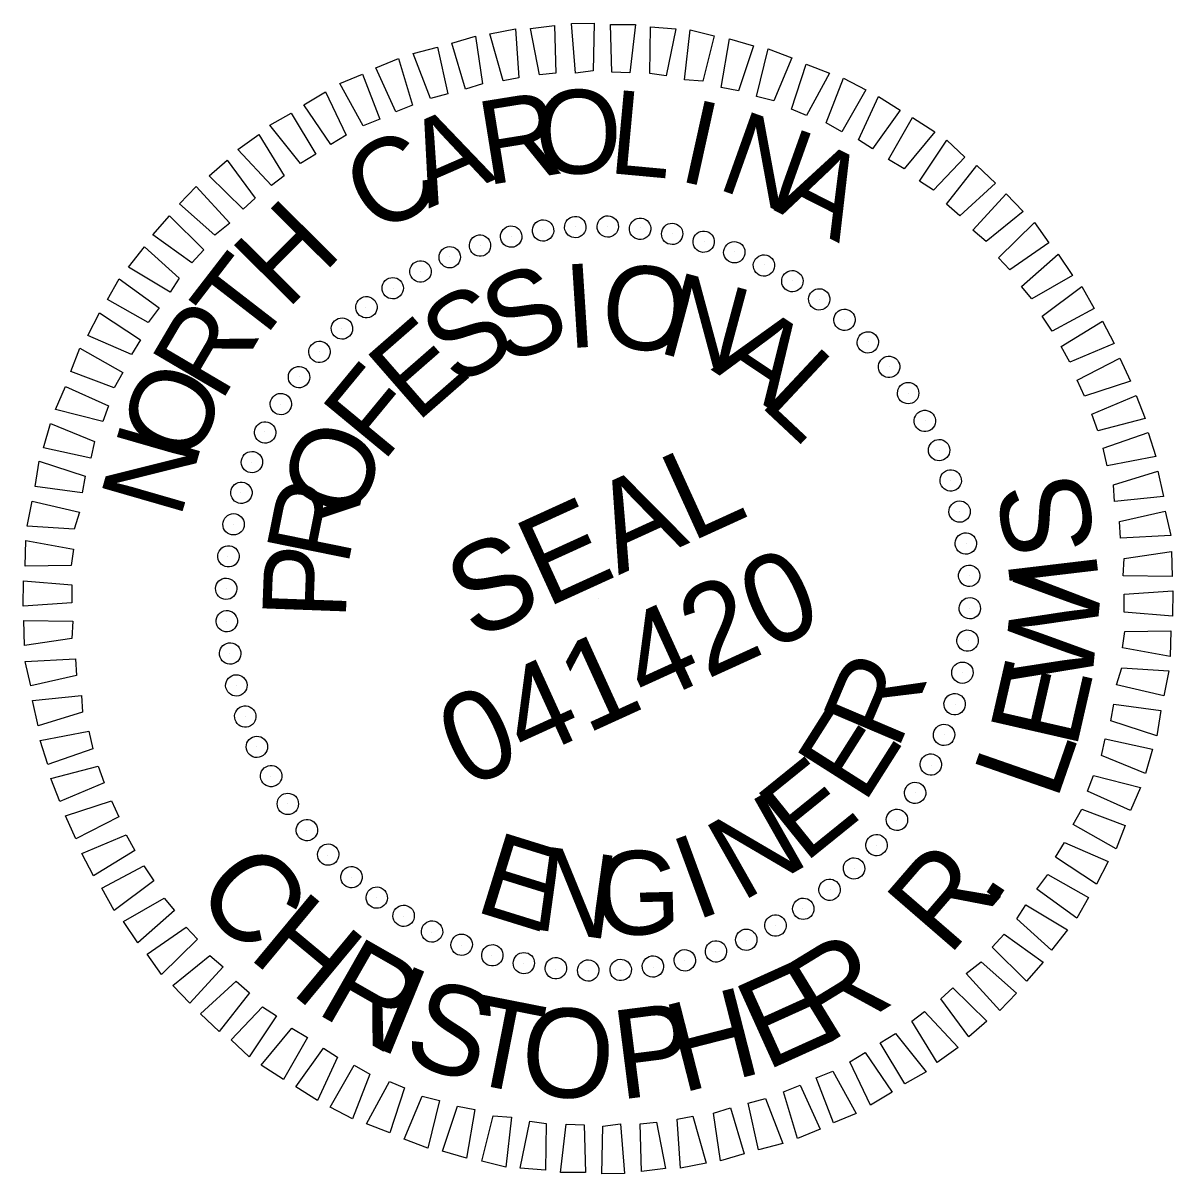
# Model space of a CAD drawing. Extents: x 2246788 to 2250969, y 662010 to 664598.
# Drawn here: x 2248634.4 to 2248712, y 663700.9 to 663778.5 of the extents above; entities that cross this region are included whole.
import ezdxf

# ---------------------------------------------------------------- set-up
doc = ezdxf.new("R2010")
doc.units = 0
doc.layers.add('Sheet PE Seal Cell', color=7, linetype='Continuous')

msp = doc.modelspace()

# ---------------------------------------------------------------- linework, layer by layer
at = {"layer": 'Sheet PE Seal Cell'}
for p, q in [((2248671.685, 663764.801), (2248671.685, 663764.801)), ((2248673.878, 663764.811), (2248673.878, 663764.811)), ((2248676.067, 663764.71), (2248676.067, 663764.71)), ((2248667.386, 663764.106), (2248667.386, 663764.106)), ((2248669.483, 663764.567), (2248669.483, 663764.567)), ((2248678.223, 663764.319), (2248678.223, 663764.319)), ((2248665.284, 663763.533), (2248665.284, 663763.533)), ((2248680.375, 663763.816), (2248680.375, 663763.816)), ((2248682.408, 663763.093), (2248682.408, 663763.093)), ((2248663.22, 663762.757), (2248663.22, 663762.757)), ((2248661.239, 663761.799), (2248661.239, 663761.799)), ((2248684.457, 663762.214), (2248684.457, 663762.214)), ((2248686.32, 663761.14), (2248686.32, 663761.14)), ((2248659.407, 663760.635), (2248659.407, 663760.635)), ((2248657.571, 663759.358), (2248657.571, 663759.358)), ((2248688.154, 663759.888), (2248688.154, 663759.888)), ((2248689.873, 663758.528), (2248689.873, 663758.528)), ((2248655.909, 663757.941), (2248655.909, 663757.941)), ((2248691.43, 663757.04), (2248691.43, 663757.04)), ((2248654.42, 663756.384), (2248654.42, 663756.384)), ((2248692.847, 663755.378), (2248692.847, 663755.378)), ((2248653.061, 663754.666), (2248653.061, 663754.666)), ((2248694.123, 663753.542), (2248694.123, 663753.542)), ((2248651.808, 663752.831), (2248651.808, 663752.831)), ((2248695.288, 663751.709), (2248695.288, 663751.709)), ((2248650.734, 663750.968), (2248650.734, 663750.968)), ((2248696.246, 663749.728), (2248696.246, 663749.728)), ((2248649.855, 663748.919), (2248649.855, 663748.919)), ((2248697.021, 663747.664), (2248697.021, 663747.664)), ((2248649.133, 663746.887), (2248649.133, 663746.887)), ((2248697.594, 663745.563), (2248697.594, 663745.563)), ((2248648.63, 663744.734), (2248648.63, 663744.734)), ((2248698.056, 663743.465), (2248698.056, 663743.465)), ((2248648.239, 663742.578), (2248648.239, 663742.578)), ((2248698.289, 663741.264), (2248698.289, 663741.264)), ((2248648.137, 663740.389), (2248648.137, 663740.389)), ((2248673.219, 663739.73), (2248673.219, 663739.73)), ((2248698.3, 663739.071), (2248698.3, 663739.071)), ((2248648.148, 663738.196), (2248648.148, 663738.196)), ((2248698.198, 663736.882), (2248698.198, 663736.882)), ((2248648.381, 663735.995), (2248648.381, 663735.995)), ((2248697.807, 663734.725), (2248697.807, 663734.725)), ((2248648.843, 663733.897), (2248648.843, 663733.897)), ((2248697.305, 663732.573), (2248697.305, 663732.573)), ((2248649.416, 663731.795), (2248649.416, 663731.795)), ((2248696.582, 663730.541), (2248696.582, 663730.541)), ((2248650.192, 663729.731), (2248650.192, 663729.731)), ((2248695.703, 663728.491), (2248695.703, 663728.491)), ((2248651.149, 663727.75), (2248651.149, 663727.75)), ((2248694.629, 663726.628), (2248694.629, 663726.628)), ((2248652.314, 663725.918), (2248652.314, 663725.918)), ((2248693.377, 663724.794), (2248693.377, 663724.794)), ((2248653.59, 663724.082), (2248653.59, 663724.082)), ((2248692.017, 663723.075), (2248692.017, 663723.075)), ((2248655.007, 663722.42), (2248655.007, 663722.42)), ((2248690.529, 663721.518), (2248690.529, 663721.518)), ((2248656.564, 663720.932), (2248656.564, 663720.932)), ((2248688.866, 663720.101), (2248688.866, 663720.101)), ((2248658.283, 663719.572), (2248658.283, 663719.572)), ((2248660.117, 663718.32), (2248660.117, 663718.32)), ((2248687.03, 663718.825), (2248687.03, 663718.825)), ((2248685.198, 663717.661), (2248685.198, 663717.661)), ((2248661.98, 663717.246), (2248661.98, 663717.246)), ((2248683.217, 663716.703), (2248683.217, 663716.703)), ((2248664.029, 663716.366), (2248664.029, 663716.366)), ((2248681.153, 663715.927), (2248681.153, 663715.927)), ((2248666.062, 663715.644), (2248666.062, 663715.644)), ((2248668.214, 663715.141), (2248668.214, 663715.141)), ((2248679.051, 663715.354), (2248679.051, 663715.354)), ((2248670.37, 663714.75), (2248670.37, 663714.75)), ((2248672.559, 663714.649), (2248672.559, 663714.649)), ((2248674.753, 663714.659), (2248674.753, 663714.659)), ((2248676.954, 663714.893), (2248676.954, 663714.893))]:
    msp.add_line(p, q, dxfattribs=at)
for points in [[(2248666.826, 663774.62), (2248665.933, 663777.785), (2248667.646, 663778.125), (2248667.885, 663774.828)], [(2248669.279, 663775.023), (2248668.676, 663778.155), (2248670.294, 663778.343), (2248670.38, 663775.14)], [(2248671.7, 663775.137), (2248671.44, 663778.481), (2248672.963, 663778.515), (2248672.891, 663775.296)], [(2248674.141, 663775.206), (2248674.055, 663778.409), (2248675.756, 663778.414), (2248675.37, 663775.162)], [(2248676.711, 663775.113), (2248676.758, 663778.266), (2248678.475, 663778.115), (2248677.824, 663774.961)], [(2248679.045, 663774.693), (2248679.435, 663778.058), (2248681.053, 663777.642), (2248680.295, 663774.604)], [(2248664.277, 663774.063), (2248663.36, 663777.161), (2248664.965, 663777.618), (2248665.431, 663774.424)], [(2248681.533, 663774.178), (2248682.076, 663777.448), (2248683.715, 663776.986), (2248682.687, 663773.935)], [(2248661.927, 663773.432), (2248660.762, 663776.472), (2248662.387, 663776.883), (2248663.102, 663773.747)], [(2248683.904, 663773.556), (2248684.692, 663776.772), (2248686.281, 663776.177), (2248685.08, 663773.267)], [(2248659.59, 663772.532), (2248658.242, 663775.489), (2248659.765, 663776.128), (2248660.703, 663772.984)], [(2248686.268, 663772.71), (2248687.25, 663775.74), (2248688.839, 663775.145), (2248687.282, 663772.293)], [(2248657.385, 663771.582), (2248655.81, 663774.436), (2248657.332, 663775.074), (2248658.498, 663772.034)], [(2248688.607, 663771.797), (2248689.767, 663774.799), (2248691.282, 663774.006), (2248689.658, 663771.178)], [(2248655.214, 663770.318), (2248653.387, 663773.002), (2248654.851, 663773.888), (2248656.244, 663770.952)], [(2248690.78, 663770.645), (2248692.139, 663773.572), (2248693.605, 663772.646), (2248691.72, 663770.029)], [(2248653.155, 663769.05), (2248651.1, 663771.63), (2248652.539, 663772.45), (2248654.184, 663769.684)], [(2248692.813, 663769.319), (2248694.437, 663772.146), (2248695.923, 663771.175), (2248693.865, 663768.699)], [(2248651.199, 663767.554), (2248648.937, 663769.985), (2248650.339, 663771.008), (2248652.051, 663768.217)], [(2248694.908, 663767.856), (2248696.731, 663770.609), (2248697.965, 663769.468), (2248695.848, 663767.24)], [(2248649.284, 663765.967), (2248646.994, 663768.22), (2248648.218, 663769.272), (2248650.095, 663766.721)], [(2248696.71, 663766.314), (2248698.772, 663768.902), (2248700.027, 663767.716), (2248697.621, 663765.52)], [(2248647.387, 663764.223), (2248645.001, 663766.323), (2248646.117, 663767.491), (2248648.4, 663765.015)], [(2248698.503, 663764.549), (2248700.74, 663766.996), (2248701.883, 663765.814), (2248699.394, 663763.801)], [(2248645.82, 663762.356), (2248643.203, 663764.24), (2248644.323, 663765.52), (2248646.634, 663763.221)], [(2248700.227, 663762.696), (2248702.662, 663765.07), (2248703.619, 663763.693), (2248700.98, 663761.886)], [(2248644.361, 663760.372), (2248641.558, 663762.062), (2248642.637, 663763.433), (2248644.977, 663761.312)], [(2248701.768, 663760.761), (2248704.24, 663762.932), (2248705.218, 663761.509), (2248702.476, 663759.93)], [(2248642.878, 663758.322), (2248640.137, 663759.876), (2248640.926, 663761.279), (2248643.63, 663759.324)], [(2248703.172, 663758.764), (2248705.84, 663760.749), (2248706.681, 663759.264), (2248703.852, 663757.755)], [(2248641.771, 663756.17), (2248638.819, 663757.462), (2248639.612, 663758.977), (2248642.366, 663757.155)], [(2248704.441, 663756.704), (2248707.232, 663758.416), (2248708.028, 663756.911), (2248705.029, 663755.654)], [(2248640.593, 663753.93), (2248637.679, 663755.019), (2248638.274, 663756.609), (2248641.168, 663754.961)], [(2248705.523, 663754.45), (2248708.418, 663755.934), (2248709.123, 663754.387), (2248706.02, 663753.358)], [(2248639.818, 663751.653), (2248636.647, 663752.461), (2248637.308, 663754.026), (2248640.214, 663752.713)], [(2248706.514, 663752.155), (2248709.513, 663753.411), (2248710.106, 663751.868), (2248706.92, 663751.021)], [(2248639.013, 663749.198), (2248635.838, 663749.895), (2248636.3, 663751.534), (2248639.277, 663750.308)], [(2248707.282, 663749.867), (2248710.318, 663750.921), (2248710.841, 663749.291), (2248707.552, 663748.671)], [(2248638.436, 663746.848), (2248635.274, 663747.275), (2248635.537, 663748.988), (2248638.633, 663747.982)], [(2248707.975, 663747.381), (2248710.962, 663748.302), (2248711.348, 663746.61), (2248708.046, 663746.259)], [(2248637.9, 663744.406), (2248634.73, 663744.609), (2248635.06, 663746.298), (2248638.255, 663745.556)], [(2248708.379, 663744.927), (2248711.469, 663745.621), (2248711.835, 663743.975), (2248708.45, 663743.806)], [(2248637.7, 663741.952), (2248634.588, 663741.907), (2248634.628, 663743.629), (2248637.852, 663743.065)], [(2248708.691, 663742.432), (2248711.885, 663742.899), (2248711.937, 663741.219), (2248708.626, 663741.249)], [(2248637.743, 663739.444), (2248634.446, 663739.205), (2248634.485, 663740.926), (2248637.742, 663740.652)], [(2248708.694, 663740.016), (2248711.991, 663740.255), (2248711.952, 663738.533), (2248708.695, 663738.807)], [(2248637.746, 663737.027), (2248634.552, 663736.561), (2248634.5, 663738.241), (2248637.811, 663738.211)], [(2248708.737, 663737.508), (2248711.849, 663737.552), (2248711.809, 663735.831), (2248708.585, 663736.395)], [(2248638.058, 663734.532), (2248634.968, 663733.838), (2248634.602, 663735.485), (2248637.987, 663735.654)], [(2248708.537, 663735.054), (2248711.707, 663734.85), (2248711.377, 663733.161), (2248708.182, 663733.903)], [(2248638.462, 663732.079), (2248635.475, 663731.157), (2248635.089, 663732.85), (2248638.391, 663733.2)], [(2248708.001, 663732.612), (2248711.163, 663732.185), (2248710.9, 663730.471), (2248707.804, 663731.478)], [(2248639.156, 663729.593), (2248636.119, 663728.539), (2248635.596, 663730.169), (2248638.885, 663730.788)], [(2248707.424, 663730.261), (2248710.599, 663729.565), (2248710.137, 663727.926), (2248707.16, 663729.152)], [(2248639.923, 663727.305), (2248636.924, 663726.048), (2248636.331, 663727.591), (2248639.517, 663728.438)], [(2248706.62, 663727.806), (2248709.79, 663726.998), (2248709.129, 663725.434), (2248706.223, 663726.747)], [(2248640.914, 663725.009), (2248638.019, 663723.525), (2248637.314, 663725.072), (2248640.417, 663726.101)], [(2248705.844, 663725.53), (2248708.758, 663724.44), (2248708.164, 663722.851), (2248705.27, 663724.499)], [(2248641.997, 663722.755), (2248639.205, 663721.043), (2248638.409, 663722.549), (2248641.408, 663723.806)], [(2248704.667, 663723.29), (2248707.618, 663721.998), (2248706.825, 663720.482), (2248704.072, 663722.305)], [(2248643.265, 663720.696), (2248640.598, 663718.711), (2248639.756, 663720.196), (2248642.585, 663721.705)], [(2248703.56, 663721.137), (2248706.3, 663719.584), (2248705.511, 663718.18), (2248702.807, 663720.135)], [(2248644.669, 663718.698), (2248642.197, 663716.528), (2248641.219, 663717.95), (2248643.961, 663719.529)], [(2248702.076, 663719.088), (2248704.879, 663717.398), (2248703.8, 663716.027), (2248701.46, 663718.148)], [(2248646.211, 663716.763), (2248643.776, 663714.39), (2248642.818, 663715.767), (2248645.457, 663717.573)], [(2248700.617, 663717.104), (2248703.234, 663715.22), (2248702.114, 663713.94), (2248699.803, 663716.238)], [(2248647.934, 663714.911), (2248645.697, 663712.463), (2248644.554, 663713.646), (2248647.043, 663715.659)], [(2248699.051, 663715.236), (2248701.436, 663713.136), (2248700.32, 663711.968), (2248698.037, 663714.445)], [(2248649.727, 663713.146), (2248647.665, 663710.557), (2248646.41, 663711.744), (2248648.816, 663713.939)], [(2248697.153, 663713.492), (2248699.443, 663711.239), (2248698.219, 663710.187), (2248696.342, 663712.739)], [(2248651.529, 663711.604), (2248649.706, 663708.85), (2248648.472, 663709.991), (2248650.589, 663712.22)], [(2248695.238, 663711.906), (2248697.5, 663709.475), (2248696.098, 663708.451), (2248694.387, 663711.243)], [(2248653.624, 663710.141), (2248652, 663707.313), (2248650.514, 663708.284), (2248652.572, 663710.761)], [(2248693.283, 663710.41), (2248695.337, 663707.83), (2248693.898, 663707.009), (2248692.253, 663709.776)], [(2248655.657, 663708.815), (2248654.298, 663705.888), (2248652.833, 663706.813), (2248654.717, 663709.43)], [(2248691.223, 663709.142), (2248693.05, 663706.458), (2248691.586, 663705.571), (2248690.193, 663708.508)], [(2248657.83, 663707.662), (2248656.671, 663704.661), (2248655.155, 663705.454), (2248656.779, 663708.282)], [(2248689.052, 663707.878), (2248690.627, 663705.024), (2248689.105, 663704.385), (2248687.939, 663707.426)], [(2248660.169, 663706.75), (2248659.187, 663703.72), (2248657.598, 663704.314), (2248659.155, 663707.167)], [(2248686.847, 663706.928), (2248688.195, 663703.971), (2248686.673, 663703.332), (2248685.734, 663706.476)], [(2248662.533, 663705.904), (2248661.746, 663702.688), (2248660.156, 663703.282), (2248661.357, 663706.192)], [(2248684.51, 663706.028), (2248685.676, 663702.988), (2248684.05, 663702.576), (2248683.335, 663705.712)], [(2248664.905, 663705.281), (2248664.361, 663702.012), (2248662.722, 663702.473), (2248663.75, 663705.524)], [(2248682.16, 663705.397), (2248683.078, 663702.298), (2248681.472, 663701.841), (2248681.006, 663705.036)], [(2248667.392, 663704.766), (2248667.002, 663701.402), (2248665.384, 663701.818), (2248666.142, 663704.856)], [(2248669.726, 663704.346), (2248669.68, 663701.193), (2248667.962, 663701.345), (2248668.613, 663704.498)], [(2248672.296, 663704.254), (2248672.382, 663701.051), (2248670.681, 663701.045), (2248671.067, 663704.298)], [(2248674.737, 663704.322), (2248674.997, 663700.979), (2248673.474, 663700.944), (2248673.546, 663704.164)], [(2248677.158, 663704.436), (2248677.761, 663701.304), (2248676.143, 663701.116), (2248676.058, 663704.319)], [(2248679.612, 663704.84), (2248680.504, 663701.675), (2248678.791, 663701.334), (2248678.552, 663704.632)]]:
    msp.add_lwpolyline(points, close=True, dxfattribs=at)
for centre, major_axis in [((2248671.688, 663764.763), (-0.044, 0.719)), ((2248673.876, 663764.801), (0.019, 0.72)), ((2248667.365, 663764.117), (-0.168, 0.7)), ((2248669.512, 663764.534), (-0.106, 0.712)), ((2248676.059, 663764.648), (0.082, 0.715)), ((2248678.22, 663764.306), (0.144, 0.706)), ((2248665.261, 663763.514), (-0.228, 0.683)), ((2248680.343, 663763.777), (0.205, 0.69)), ((2248682.411, 663763.064), (0.264, 0.67)), ((2248663.219, 663762.73), (-0.287, 0.66)), ((2248661.252, 663761.771), (-0.344, 0.633)), ((2248684.41, 663762.174), (0.321, 0.644)), ((2248686.324, 663761.114), (0.376, 0.614)), ((2248659.377, 663760.644), (-0.397, 0.6)), ((2248657.607, 663759.358), (-0.448, 0.563)), ((2248688.137, 663759.89), (0.428, 0.579)), ((2248689.838, 663758.513), (0.477, 0.539)), ((2248655.955, 663757.923), (-0.496, 0.522)), ((2248691.412, 663756.993), (0.522, 0.496)), ((2248654.435, 663756.349), (-0.539, 0.477)), ((2248692.847, 663755.342), (0.563, 0.448)), ((2248653.058, 663754.649), (-0.579, 0.428)), ((2248694.133, 663753.572), (0.6, 0.397)), ((2248651.835, 663752.835), (-0.614, 0.376)), ((2248695.26, 663751.696), (0.633, 0.344)), ((2248650.774, 663750.921), (-0.644, 0.321)), ((2248696.219, 663749.73), (0.66, 0.287)), ((2248649.884, 663748.922), (-0.67, 0.264)), ((2248697.003, 663747.687), (0.683, 0.228)), ((2248649.172, 663746.854), (-0.69, 0.205)), ((2248697.606, 663745.584), (0.7, 0.168)), ((2248648.642, 663744.731), (-0.706, 0.144)), ((2248698.023, 663743.436), (0.712, 0.106)), ((2248648.3, 663742.57), (-0.715, 0.082)), ((2248698.252, 663741.26), (0.719, 0.044)), ((2248648.147, 663740.387), (-0.72, 0.019)), ((2248698.29, 663739.072), (0.72, -0.019)), ((2248648.185, 663738.2), (-0.719, -0.044)), ((2248698.137, 663736.89), (0.715, -0.082)), ((2248648.414, 663736.024), (-0.712, -0.106)), ((2248697.795, 663734.729), (0.706, -0.144)), ((2248648.831, 663733.876), (-0.7, -0.168)), ((2248697.266, 663732.606), (0.69, -0.205)), ((2248649.434, 663731.773), (-0.683, -0.228)), ((2248696.553, 663730.537), (0.67, -0.264)), ((2248650.218, 663729.73), (-0.66, -0.287)), ((2248695.663, 663728.538), (0.644, -0.321)), ((2248651.177, 663727.763), (-0.633, -0.344)), ((2248694.602, 663726.625), (0.614, -0.376)), ((2248652.304, 663725.888), (-0.6, -0.397)), ((2248693.379, 663724.811), (0.579, -0.428)), ((2248653.59, 663724.118), (-0.563, -0.448)), ((2248692.002, 663723.111), (0.539, -0.477)), ((2248655.026, 663722.467), (-0.522, -0.496)), ((2248690.482, 663721.537), (0.496, -0.522)), ((2248656.599, 663720.947), (-0.477, -0.539)), ((2248688.831, 663720.101), (0.448, -0.563)), ((2248658.3, 663719.57), (-0.428, -0.579)), ((2248660.114, 663718.346), (-0.376, -0.614)), ((2248687.06, 663718.815), (0.397, -0.6)), ((2248662.027, 663717.285), (-0.321, -0.644)), ((2248685.185, 663717.689), (0.344, -0.633)), ((2248683.218, 663716.73), (0.287, -0.66)), ((2248664.026, 663716.395), (-0.264, -0.67)), ((2248681.176, 663715.946), (0.228, -0.683)), ((2248666.095, 663715.683), (-0.205, -0.69)), ((2248668.218, 663715.153), (-0.144, -0.706)), ((2248679.073, 663715.343), (0.168, -0.7)), ((2248670.379, 663714.811), (-0.082, -0.715)), ((2248672.561, 663714.658), (-0.019, -0.72)), ((2248674.749, 663714.697), (0.044, -0.719)), ((2248676.925, 663714.925), (0.106, -0.712))]:
    msp.add_ellipse(centre, major_axis=major_axis, ratio=0.999708, dxfattribs=at)

# ---------------------------------------------------------------- texts
for s, height, rotation, p in [('O', 5.638, 1.91911, (2248669.058, 663768.274)), ('L', 5.638, 354.71882, (2248673.829, 663768.415)), ('R', 5.638, 9.11904, (2248665.698, 663767.568)), ('I', 5.638, 347.51808, (2248678.509, 663767.911)), ('N', 5.639, 340.31685, (2248681.109, 663767.392)), ('A', 5.638, 23.51826, (2248661.794, 663766.008)), ('C', 5.638, 30.71781, (2248658.324, 663764.097)), ('A', 5.639, 333.1151, (2248685.016, 663765.93)), ('H', 5.638, 45.11742, (2248652.237, 663759.126)), ('T', 5.638, 52.31772, (2248649.964, 663756.277)), ('S', 5.638, 22.39834, (2248666.939, 663755.44)), ('I', 5.638, 3.68755, (2248671.142, 663756.586)), ('O', 5.638, 354.33143, (2248673.252, 663756.779)), ('N', 5.638, 344.97455, (2248677.13, 663756.348)), ('S', 5.638, 31.75355, (2248663.684, 663753.902)), ('R', 5.639, 59.51845, (2248647.782, 663752.865)), ('E', 5.638, 41.10901, (2248660.98, 663751.516)), ('A', 5.639, 326.25821, (2248680.801, 663755.164)), ('L', 5.639, 316.89879, (2248684.006, 663752.833)), ('F', 5.638, 50.46498, (2248658.69, 663748.824)), ('O', 5.639, 66.71968, (2248645.928, 663748.613)), ('N', 5.639, 73.92144, (2248645.038, 663745.021)), ('O', 5.639, 69.17918, (2248656.91, 663744.771)), ('SEAL', 5.9982, 24.49794, (2248664.86, 663736.853)), ('S', 5.998, 100.55241, (2248706.865, 663743.131)), ('R', 5.639, 78.53759, (2248656.333, 663741.816)), ('P', 5.639, 87.89683, (2248656.204, 663738.241)), ('041420', 5.9982, 24.49794, (2248664.31, 663726.87)), ('I', 5.998, 96.75046, (2248707.017, 663740.893)), ('W', 5.998, 84.21639, (2248706.464, 663733.53)), ('R', 5.639, 66.97935, (2248693.409, 663729.424)), ('E', 5.998, 77.10705, (2248705.441, 663729.463)), ('E', 5.638, 57.62203, (2248691.153, 663725.814)), ('L', 5.998, 70.83229, (2248704.126, 663726.003)), ('E', 5.638, 38.9097, (2248687.139, 663721.842)), ('N', 5.638, 29.55433, (2248682.884, 663719.243)), ('E', 5.638, 342.77483, (2248664.784, 663718.688)), ('I', 5.638, 20.19914, (2248679.773, 663717.991)), ('N', 5.639, 352.1319, (2248668.634, 663717.475)), ('G', 5.638, 1.48818, (2248673.025, 663717.004)), ('R', 5.998, 49.11789, (2248696.854, 663715.542)), ('C', 5.998, 310.69992, (2248645.831, 663719.89)), ('.', 5.998, 56.59815, (2248699.801, 663718.825)), ('H', 5.998, 320.28207, (2248649.516, 663715.608)), ('R', 5.998, 330.26605, (2248654.057, 663711.864)), ('R', 5.998, 31.43728, (2248688.391, 663709.506)), ('E', 5.998, 24.32794, (2248684.534, 663707.861)), ('I', 5.998, 337.74631, (2248657.848, 663709.607)), ('S', 5.998, 341.54826, (2248659.879, 663708.654)), ('H', 5.998, 14.34395, (2248678.837, 663706.382)), ('T', 5.998, 348.87397, (2248663.95, 663707.206)), ('O', 5.998, 355.67421, (2248667.867, 663706.338)), ('P', 5.998, 7.23461, (2248674.667, 663705.943))]:
    msp.add_text(s, height=height, rotation=rotation, dxfattribs=at).set_placement(p)

doc.saveas('drawing.dxf')
